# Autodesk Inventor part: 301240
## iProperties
Created: 2007-12
Part Number: 301240
Document SubType Name: Modeling
Designer: TH
Density: 8.08 g/cm^3
Mass: 31.9322 g
Surface Area: 31.3978 cm^2
Volume: 3.95201 cm^3
Material: Stainless Steel
Description: PIVOT CAM BUSHING
Component Category: Back Component
Author: TH
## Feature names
1. Revolution1
2. Chamfer1
3. Chamfer2
4. Chamfer3
5. Extrusion1
6. Extrusion2
7. Fillet1
8. Extrusion3
